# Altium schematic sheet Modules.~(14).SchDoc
size A4
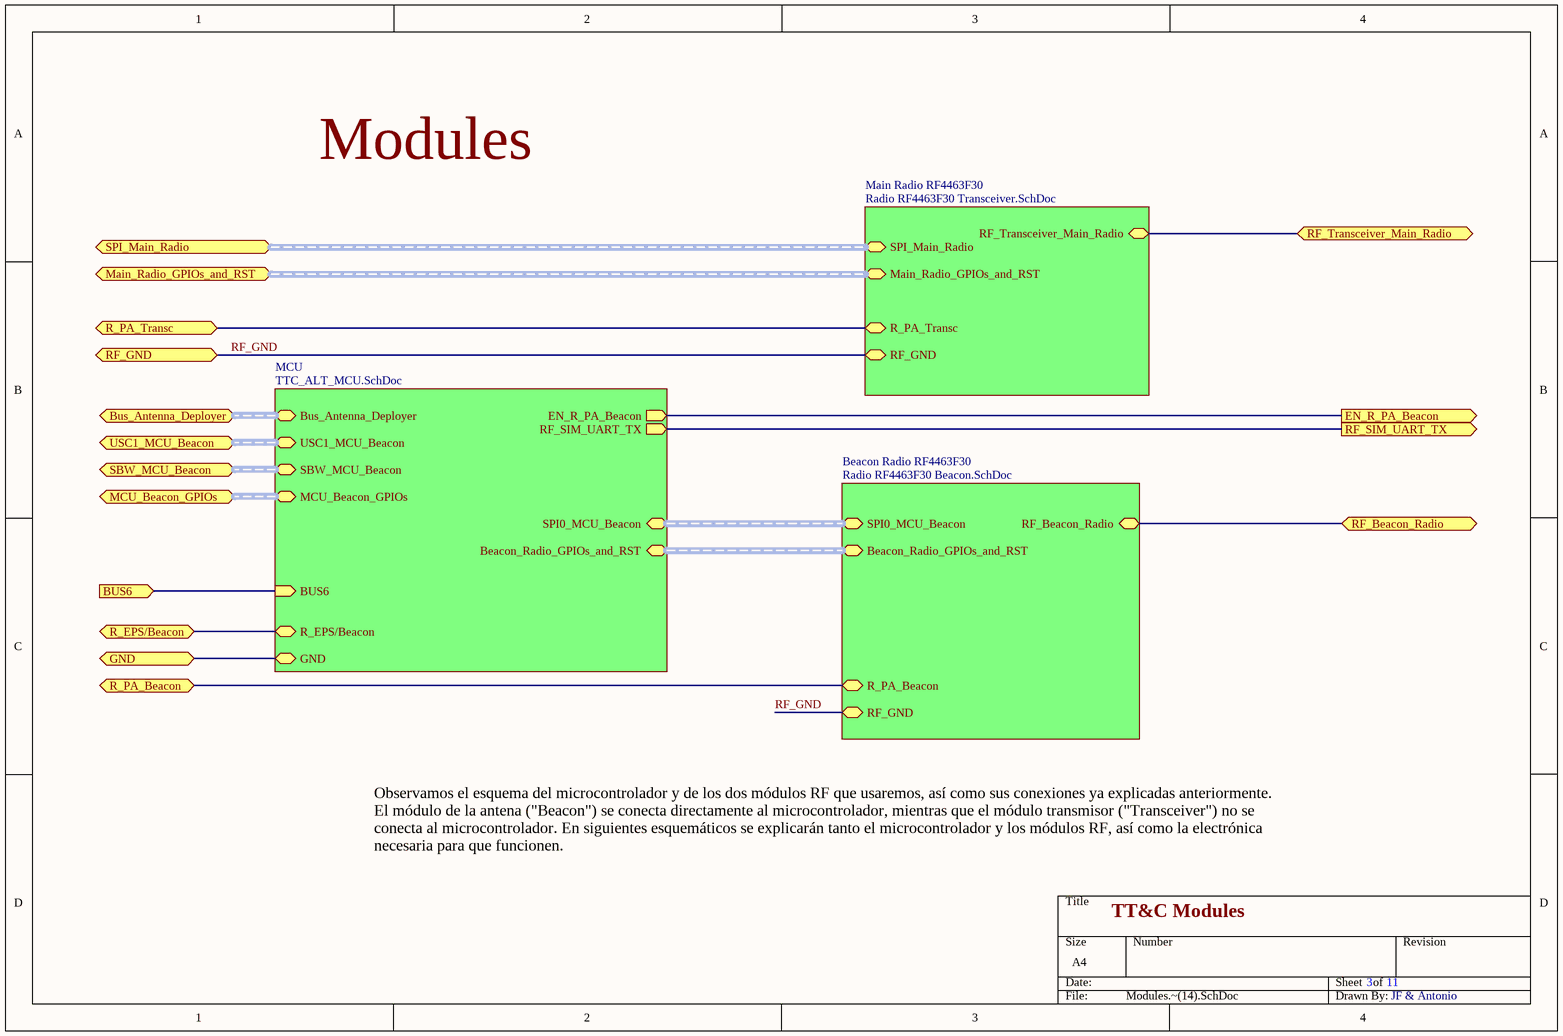
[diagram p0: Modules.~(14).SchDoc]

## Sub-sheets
Beacon Radio RF4463F30 = Radio RF4463F30 Beacon.SchDoc: SPI0_MCU_Beacon, Beacon_Radio_GPIOs_and_RST, R_PA_Beacon, RF_GND, RF_Beacon_Radio
Main Radio RF4463F30 = Radio RF4463F30 Transceiver.SchDoc: RF_Transceiver_Main_Radio, R_PA_Transc, RF_GND, SPI_Main_Radio, Main_Radio_GPIOs_and_RST
MCU = TTC_ALT_MCU.SchDoc: BUS6, R_EPS/Beacon, GND, SBW_MCU_Beacon, Bus_Antenna_Deployer, USC1_MCU_Beacon, MCU_Beacon_GPIOs, EN_R_PA_Beacon, RF_SIM_UART_TX, SPI0_MCU_Beacon, Beacon_Radio_GPIOs_and_RST

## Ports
BUS6, Bus_Antenna_Deployer, EN_R_PA_Beacon, GND, Main_Radio_GPIOs_and_RST, MCU_Beacon_GPIOs, R_EPS/Beacon, R_PA_Beacon, R_PA_Transc, RF_Beacon_Radio, RF_GND, RF_SIM_UART_TX, RF_Transceiver_Main_Radio, SBW_MCU_Beacon, SPI_Main_Radio, USC1_MCU_Beacon

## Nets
BUS6: port BUS6, sheet MCU/BUS6
EN_R_PA_Beacon: port EN_R_PA_Beacon, sheet MCU/EN_R_PA_Beacon
GND: port GND, sheet MCU/GND
R_EPS/Beacon: port R_EPS/Beacon, sheet MCU/R_EPS/Beacon
R_PA_Beacon: port R_PA_Beacon, sheet Beacon Radio RF4463F30/R_PA_Beacon
R_PA_Transc: port R_PA_Transc, sheet Main Radio RF4463F30/R_PA_Transc
RF_Beacon_Radio: port RF_Beacon_Radio, sheet Beacon Radio RF4463F30/RF_Beacon_Radio
RF_GND: port RF_GND, sheet Main Radio RF4463F30/RF_GND, sheet Beacon Radio RF4463F30/RF_GND
RF_SIM_UART_TX: port RF_SIM_UART_TX, sheet MCU/RF_SIM_UART_TX
RF_Transceiver_Main_Radio: port RF_Transceiver_Main_Radio, sheet Main Radio RF4463F30/RF_Transceiver_Main_Radio

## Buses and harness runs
harness port Bus_Antenna_Deployer = sheet MCU/Bus_Antenna_Deployer
harness port Main_Radio_GPIOs_and_RST = sheet Main Radio RF4463F30/Main_Radio_GPIOs_and_RST
harness port MCU_Beacon_GPIOs = sheet MCU/MCU_Beacon_GPIOs
harness port SBW_MCU_Beacon = sheet MCU/SBW_MCU_Beacon
harness port SPI_Main_Radio = sheet Main Radio RF4463F30/SPI_Main_Radio
harness port USC1_MCU_Beacon = sheet MCU/USC1_MCU_Beacon
harness sheet Beacon Radio RF4463F30/Beacon_Radio_GPIOs_and_RST = sheet MCU/Beacon_Radio_GPIOs_and_RST
harness sheet Beacon Radio RF4463F30/SPI0_MCU_Beacon = sheet MCU/SPI0_MCU_Beacon

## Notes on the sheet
- Modules
- TT&C Modules
- Observamos el esquema del microcontrolador y de los dos módulos RF que usaremos, así como sus conexiones ya explicadas anteriormente. El módulo de la antena ("Beacon") se conecta directamente al microcontrolador, mientras que el módulo transmisor ("Transceiver") no se conecta al microcontrolador. En siguientes esquemáticos se explicarán tanto el microcontrolador y los módulos RF, así como la electrónica necesaria para que funcionen.
- 3
- 11
- JF & Antonio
